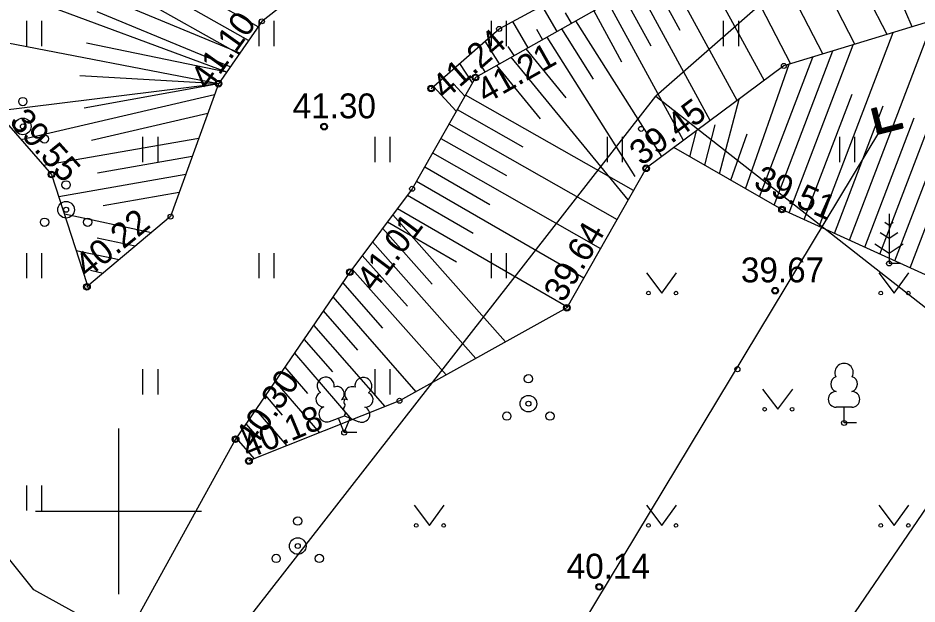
# Model space of a CAD drawing. Extents: x 641898 to 642452, y 6471715 to 6472255.
# Drawn here: x 641996.97 to 642024.06, y 6472097.21 to 6472114.87 of the extents above; entities that cross this region are included whole.
import ezdxf

# ---------------------------------------------------------------- set-up
doc = ezdxf.new("R2010")
doc.units = 0
for name, color, linetype in [('HALJASTUS', 7, 'Continuous'), ('KORGUS-EH2000', 7, 'Continuous'), ('MOOTMPUNKT', 7, 'Continuous'), ('MOOTPIIR', 7, 'Continuous'), ('PIIR', 7, 'Continuous'), ('PUU', 7, 'Continuous'), ('RELJEEF', 7, 'Continuous'), ('SKTRASS', 7, 'Continuous'), ('VORK', 7, 'Continuous')]:
    doc.layers.add(name, color=color, linetype=linetype)

msp = doc.modelspace()

# ---------------------------------------------------------------- linework, layer by layer
at = {"layer": 'HALJASTUS'}
for p, q in [((641997.225, 6472114.782), (641997.225, 6472114.021)), ((641997.68, 6472114.782), (641997.68, 6472114.021)), ((642004.225, 6472114.782), (642004.225, 6472114.021)), ((642004.68, 6472114.782), (642004.68, 6472114.021)), ((642011.225, 6472114.782), (642011.225, 6472114.021)), ((642011.68, 6472114.782), (642011.68, 6472114.021)), ((642018.225, 6472114.782), (642018.225, 6472114.021)), ((642018.68, 6472114.782), (642018.68, 6472114.021)), ((642000.725, 6472111.282), (642000.725, 6472110.521)), ((642001.18, 6472111.282), (642001.18, 6472110.521)), ((642007.725, 6472111.282), (642007.725, 6472110.521)), ((642008.18, 6472111.282), (642008.18, 6472110.521)), ((642014.725, 6472111.282), (642014.725, 6472110.521)), ((642015.18, 6472111.282), (642015.18, 6472110.521)), ((642021.725, 6472111.282), (642021.725, 6472110.521)), ((642022.18, 6472111.282), (642022.18, 6472110.521)), ((641997.225, 6472107.782), (641997.225, 6472107.021)), ((641997.68, 6472107.782), (641997.68, 6472107.021)), ((642004.225, 6472107.782), (642004.225, 6472107.021)), ((642004.68, 6472107.782), (642004.68, 6472107.021)), ((642011.225, 6472107.782), (642011.225, 6472107.021)), ((642011.68, 6472107.782), (642011.68, 6472107.021)), ((642015.908, 6472107.182), (642016.371, 6472106.575)), ((642016.371, 6472106.575), (642016.817, 6472107.182)), ((642022.908, 6472107.182), (642023.371, 6472106.575)), ((642023.371, 6472106.575), (642023.817, 6472107.182)), ((642000.725, 6472104.282), (642000.725, 6472103.521)), ((642001.18, 6472104.282), (642001.18, 6472103.521)), ((642007.725, 6472104.282), (642007.725, 6472103.521)), ((642008.18, 6472104.282), (642008.18, 6472103.521)), ((642019.408, 6472103.682), (642019.871, 6472103.075)), ((642019.871, 6472103.075), (642020.317, 6472103.682)), ((641997.225, 6472100.782), (641997.225, 6472100.021)), ((641997.68, 6472100.782), (641997.68, 6472100.021)), ((642008.908, 6472100.182), (642009.371, 6472099.575)), ((642009.371, 6472099.575), (642009.817, 6472100.182)), ((642015.908, 6472100.182), (642016.371, 6472099.575)), ((642016.371, 6472099.575), (642016.817, 6472100.182)), ((642022.908, 6472100.182), (642023.371, 6472099.575)), ((642023.371, 6472099.575), (642023.817, 6472100.182))]:
    msp.add_line(p, q, dxfattribs=at)
msp.add_lwpolyline([(642003.529, 6472102.174), (642000.861, 6472097.337), (641998.193, 6472092.499)], dxfattribs=at)
for centre in [(642015.97, 6472106.575), (642016.799, 6472106.575), (642022.97, 6472106.575), (642023.799, 6472106.575), (642019.47, 6472103.075), (642020.299, 6472103.075), (642008.97, 6472099.575), (642009.799, 6472099.575), (642015.97, 6472099.575), (642016.799, 6472099.575), (642022.97, 6472099.575), (642023.799, 6472099.575)]:
    msp.add_circle(centre, 0.055, dxfattribs=at)
at = {"layer": 'KORGUS-EH2000'}
for centre in [(642003.015, 6472112.887), (642010.755, 6472113.076), (642009.422, 6472112.742), (642006.193, 6472111.593), (642015.898, 6472110.337), (641997.98, 6472110.147), (642019.993, 6472109.094), (642006.969, 6472107.208), (641999.049, 6472106.763), (642019.787, 6472106.649), (642013.512, 6472106.135), (642003.529, 6472102.174), (642003.93, 6472101.516), (642014.487, 6472097.721)]:
    msp.add_circle(centre, 0.1, dxfattribs=at)
at = {"layer": 'MOOTMPUNKT'}
for centre in [(642004.319, 6472114.766), (642011.469, 6472114.538), (642020.049, 6472113.422), (642010.755, 6472113.076), (642003.015, 6472112.887), (642009.422, 6472112.742), (641997.116, 6472111.599), (642006.193, 6472111.593), (642015.746, 6472111.526), (642022.933, 6472111.454), (642015.898, 6472110.337), (641997.98, 6472110.147), (642008.847, 6472109.72), (641998.42, 6472109.088), (642001.569, 6472108.88), (642019.993, 6472109.094), (642006.969, 6472107.208), (642023.219, 6472107.468), (641999.049, 6472106.763), (642019.787, 6472106.649), (642013.512, 6472106.135), (642018.65, 6472104.28), (642008.467, 6472103.33), (642012.351, 6472103.243), (642021.863, 6472102.662), (642006.801, 6472102.371), (642003.529, 6472102.174), (642003.93, 6472101.516), (642005.4, 6472098.953), (642014.487, 6472097.721)]:
    msp.add_circle(centre, 0.075, dxfattribs=at)
at = {"layer": 'MOOTPIIR'}
msp.add_lwpolyline([(642014.306, 6472085.384), (642027.67, 6472104.979), (642055.501, 6472084.843), (642081.563, 6472094.262), (642123.938, 6472142.273), (642065.721, 6472244.475), (642008.922, 6472196.948), (642003.347, 6472200.453), (641979.65, 6472162.756), (641979.65, 6472162.756), (641986.045, 6472158.736), (642004.269, 6472142.365), (641987.048, 6472123.488), (641970.482, 6472097.889), (641986.758, 6472084.396)], close=True, dxfattribs=at)
at = {"layer": 'PIIR'}
for p, q in [((642094.72, 6472181.39), (642016.19, 6472112.51)), ((642002.45, 6472094.89), (642016.19, 6472112.51)), ((642016.19, 6472112.51), (642089.96, 6472054.66)), ((641997.45, 6472097.63), (641993.3, 6472102.74)), ((642002.45, 6472094.89), (641997.45, 6472097.63))]:
    msp.add_line(p, q, dxfattribs=at)
at = {"layer": 'PUU'}
for p, q in [((642023.219, 6472108.968), (642023.219, 6472107.468)), ((642023.219, 6472108.618), (642023.095, 6472108.701)), ((642023.343, 6472108.701), (642023.219, 6472108.618)), ((642023.219, 6472108.218), (642022.952, 6472108.396)), ((642023.486, 6472108.396), (642023.219, 6472108.218)), ((642022.795, 6472108.057), (642023.219, 6472107.775)), ((642023.219, 6472107.775), (642023.643, 6472108.057)), ((642023.579, 6472107.468), (642023.219, 6472107.468)), ((642022.103, 6472103.137), (642021.623, 6472103.137)), ((642021.863, 6472102.662), (642021.863, 6472103.137)), ((642006.361, 6472102.706), (642006.806, 6472102.881)), ((642006.801, 6472102.371), (642006.626, 6472102.811)), ((642006.801, 6472102.371), (642006.981, 6472102.811)), ((642006.806, 6472102.881), (642007.246, 6472102.701)), ((642022.243, 6472102.662), (642021.863, 6472102.662)), ((642007.181, 6472102.371), (642006.801, 6472102.371))]:
    msp.add_line(p, q, dxfattribs=at)
msp.add_lwpolyline([(642006.806, 6472103.376), (642006.786, 6472103.301), (642006.786, 6472103.281), (642006.796, 6472103.251), (642006.816, 6472103.216), (642006.821, 6472103.196), (642006.806, 6472103.161), (642006.781, 6472103.111), (642006.776, 6472103.086), (642006.781, 6472103.071), (642006.791, 6472103.041), (642006.826, 6472102.981), (642006.831, 6472102.961), (642006.826, 6472102.941), (642006.811, 6472102.906), (642006.806, 6472102.881)], dxfattribs=at)
for centre, radius in [((641997.116, 6472112.349), 0.125), ((641997.116, 6472111.599), 0.25), ((641997.766, 6472111.224), 0.125), ((641998.42, 6472109.838), 0.125), ((641998.42, 6472109.088), 0.25), ((641997.77, 6472108.713), 0.125), ((641999.07, 6472108.713), 0.125), ((642012.351, 6472103.993), 0.125), ((642012.351, 6472103.243), 0.25), ((642011.701, 6472102.868), 0.125), ((642013.001, 6472102.868), 0.125), ((642005.4, 6472099.703), 0.125), ((642005.4, 6472098.953), 0.25), ((642004.75, 6472098.578), 0.125), ((642006.05, 6472098.578), 0.125)]:
    msp.add_circle(centre, radius, dxfattribs=at)
for centre, radius, start, end in [((642021.863, 6472104.182), 0.277, 332.5799, 207.4201), ((642006.244, 6472103.785), 0.256, 350.4856, 111.5002), ((642007.38, 6472103.776), 0.256, 67.6168, 188.6314), ((642021.693, 6472103.835), 0.233, 109.0217, 253.1415), ((642022.033, 6472103.835), 0.233, 286.8508, 70.9859), ((642006.244, 6472103.785), 0.256, 111.5027, 232.5173), ((642006.579, 6472103.535), 0.224, 308.5041, 111.5725), ((642007.042, 6472103.53), 0.225, 67.7016, 230.5126), ((642007.38, 6472103.776), 0.256, 306.5997, 67.6143), ((642006.17, 6472103.374), 0.224, 111.4304, 274.4987), ((642007.447, 6472103.364), 0.224, 264.6183, 67.6866), ((642021.626, 6472103.374), 0.238, 90.0016, 269.3953), ((642022.1, 6472103.374), 0.238, 270.6047, 89.9984), ((642006.805, 6472103.138), 0.237, 66.7655, 111.5015), ((642006.275, 6472102.929), 0.237, 111.5014, 291.5004), ((642007.336, 6472102.921), 0.237, 247.6166, 67.6155)]:
    msp.add_arc(centre, radius, start, end, dxfattribs=at)
at = {"layer": 'RELJEEF'}
for p, q in [((642023.912, 6472114.6), (642021.981, 6472119.162)), ((642023.165, 6472114.373), (642020.963, 6472118.661)), ((642003.919, 6472114.19), (641996.111, 6472118.591)), ((642022.193, 6472114.076), (642020.065, 6472118.219)), ((642019.168, 6472117.777), (642021.221, 6472113.78)), ((642018.281, 6472117.316), (642020.249, 6472113.483)), ((642003.656, 6472113.811), (641995.446, 6472117.206)), ((642004.206, 6472114.603), (642000.235, 6472116.841)), ((642017.371, 6472116.803), (642019.453, 6472112.979)), ((642003.259, 6472113.239), (641995.155, 6472116.244)), ((642018.643, 6472112.377), (642016.499, 6472116.312)), ((642003.633, 6472113.778), (641999.744, 6472115.969)), ((642016.064, 6472116.067), (642016.916, 6472114.502)), ((642017.832, 6472111.775), (642015.628, 6472115.821)), ((642015.192, 6472115.576), (642016.038, 6472114.023)), ((642013.216, 6472114.462), (642012.763, 6472115.237)), ((642017.022, 6472111.172), (642014.757, 6472115.33)), ((642003.365, 6472113.391), (641999.355, 6472115.049)), ((642013.651, 6472114.708), (642013.466, 6472115.025)), ((642014.321, 6472115.085), (642015.16, 6472113.545)), ((642012.344, 6472113.971), (642011.882, 6472114.761)), ((642016.376, 6472110.693), (642013.784, 6472114.783)), ((642022.029, 6472108.167), (642024.518, 6472114.696)), ((642003.015, 6472112.887), (641995.086, 6472114.406)), ((642012.78, 6472114.217), (642012.603, 6472114.52)), ((642013.348, 6472114.537), (642014.306, 6472113.025)), ((642021.118, 6472108.582), (642023.346, 6472114.428)), ((642022.941, 6472107.752), (642025.541, 6472114.572)), ((642023.853, 6472107.337), (642026.564, 6472114.448)), ((642003.259, 6472113.239), (641999.032, 6472114.106)), ((642011.485, 6472113.487), (642011.046, 6472114.167)), ((642015.572, 6472110.094), (642012.912, 6472114.291)), ((642020.206, 6472108.997), (642022.135, 6472114.058)), ((642011.922, 6472113.733), (642011.743, 6472114.009)), ((642012.276, 6472113.933), (642013.483, 6472112.46)), ((642019.759, 6472109.228), (642021.529, 6472113.874)), ((642015.357, 6472109.384), (642011.834, 6472113.684)), ((642019.319, 6472109.48), (642020.924, 6472113.689)), ((642010.664, 6472112.916), (642010.286, 6472113.5)), ((642011.049, 6472113.242), (642010.903, 6472113.467)), ((642011.392, 6472113.435), (642012.709, 6472111.826)), ((642018.894, 6472109.723), (642020.209, 6472113.471)), ((642003.015, 6472112.887), (641998.831, 6472113.127)), ((642003.015, 6472112.887), (641996.316, 6472112.052)), ((642003.015, 6472112.887), (641998.961, 6472112.151)), ((642010.175, 6472112.056), (642009.49, 6472112.802)), ((642010.434, 6472112.512), (642010.101, 6472112.875)), ((642002.893, 6472112.549), (641997.062, 6472111.198)), ((642015.516, 6472109.664), (642010.453, 6472112.544)), ((642020.662, 6472108.79), (642022.104, 6472112.575)), ((642018.114, 6472110.17), (642018.701, 6472112.42)), ((642021.573, 6472108.374), (642023.039, 6472112.219)), ((642002.691, 6472111.989), (641999.187, 6472111.177)), ((642010.206, 6472112.11), (642012.181, 6472110.986)), ((642009.958, 6472111.675), (642015.022, 6472108.794)), ((642017.664, 6472110.428), (642017.982, 6472111.648)), ((642022.485, 6472107.959), (642023.973, 6472111.862)), ((642017.214, 6472110.685), (642017.419, 6472111.467)), ((642018.453, 6472109.976), (642018.945, 6472111.38)), ((642023.397, 6472107.544), (642024.908, 6472111.506)), ((642002.419, 6472111.235), (641997.744, 6472110.417)), ((642009.711, 6472111.24), (642011.687, 6472110.116)), ((642009.464, 6472110.806), (642014.528, 6472107.924)), ((642002.223, 6472110.694), (641999.367, 6472110.194)), ((642009.226, 6472110.386), (642011.189, 6472109.249)), ((642002.028, 6472110.152), (641998.197, 6472109.482)), ((642008.979, 6472109.951), (642014.021, 6472107.031)), ((642001.832, 6472109.61), (641999.54, 6472109.209)), ((642008.706, 6472109.532), (642010.688, 6472108.383)), ((642000.991, 6472108.395), (641998.369, 6472108.952)), ((642008.261, 6472108.937), (642011.663, 6472105.107)), ((642008.405, 6472109.128), (642013.527, 6472106.161)), ((642008.103, 6472108.725), (642010.187, 6472107.518)), ((642007.956, 6472108.528), (642009.452, 6472106.844)), ((642000.506, 6472107.987), (641999.361, 6472108.23)), ((642007.65, 6472108.119), (642010.768, 6472104.609)), ((642000.02, 6472107.579), (641998.726, 6472107.854)), ((642007.344, 6472107.71), (642008.704, 6472106.18)), ((642007.039, 6472107.301), (642009.873, 6472104.112)), ((641999.535, 6472107.171), (641999.153, 6472107.252)), ((641999.049, 6472106.763), (641999.084, 6472106.756)), ((642006.754, 6472106.893), (642007.954, 6472105.518)), ((642006.462, 6472106.467), (642008.961, 6472103.605)), ((642006.171, 6472106.04), (642007.201, 6472104.86)), ((642005.879, 6472105.614), (642008.027, 6472103.154)), ((642005.588, 6472105.187), (642006.448, 6472104.203)), ((642005.3, 6472104.766), (642007.035, 6472102.758)), ((642005.009, 6472104.339), (642005.692, 6472103.548)), ((642004.717, 6472103.912), (642006.053, 6472102.365)), ((642004.425, 6472103.485), (642004.935, 6472102.895)), ((642004.133, 6472103.058), (642005.071, 6472101.972)), ((642003.841, 6472102.631), (642004.178, 6472102.241)), ((642003.549, 6472102.204), (642004.089, 6472101.579))]:
    msp.add_line(p, q, dxfattribs=at)
for points in [[(642049.525, 6472147.752), (642033.209, 6472131.238), (642029.368, 6472128.57), (642019.347, 6472123.425), (642009.733, 6472118.353), (642006.276, 6472116.303), (642004.319, 6472114.766), (642003.015, 6472112.887), (642001.569, 6472108.88), (641999.049, 6472106.763)], [(642009.422, 6472112.742), (642011.469, 6472114.538), (642021.273, 6472119.831), (642030.743, 6472124.628), (642039.752, 6472128.982), (642050.967, 6472134.85), (642058.208, 6472138.912), (642059.402, 6472139.059), (642060.171, 6472138.313), (642060.027, 6472137.169), (642058.959, 6472136.054), (642051.674, 6472131.646), (642042.143, 6472126.699), (642035.655, 6472123.419), (642032.765, 6472119.235), (642026.028, 6472115.246), (642020.049, 6472113.422), (642015.898, 6472110.337), (642013.512, 6472106.135), (642008.467, 6472103.33), (642003.93, 6472101.516)], [(642058.721, 6472137.77), (642054.392, 6472134.892), (642048.445, 6472131.824), (642038.57, 6472127.238), (642029.307, 6472122.768), (642018.627, 6472117.511), (642010.755, 6472113.076), (642008.847, 6472109.72), (642006.969, 6472107.208), (642003.529, 6472102.174)], [(641995.53, 6472112.953), (641997.98, 6472110.147), (641999.049, 6472106.863)], [(642046.898, 6472092.573), (642045.899, 6472093.597), (642045.866, 6472095.265), (642040.033, 6472099.108), (642035.046, 6472103.249), (642029.201, 6472104.902), (642019.993, 6472109.094), (642016.735, 6472110.959)]]:
    msp.add_lwpolyline(points, dxfattribs=at)
at = {"layer": 'SKTRASS'}
for p, q in [((642022.829, 6472112.157), (642022.691, 6472112.122)), ((642022.828, 6472112.157), (642022.76, 6472111.85)), ((642022.829, 6472112.157), (642022.985, 6472111.54)), ((642022.691, 6472112.122), (642022.881, 6472111.368)), ((642022.719, 6472112.129), (642022.705, 6472112.066)), ((642022.747, 6472112.136), (642022.719, 6472112.012)), ((642022.774, 6472112.143), (642022.732, 6472111.958)), ((642022.801, 6472112.15), (642022.746, 6472111.904)), ((642022.76, 6472112.14), (642022.933, 6472111.454)), ((642022.842, 6472112.105), (642022.773, 6472111.796)), ((642022.856, 6472112.051), (642022.787, 6472111.742)), ((642022.869, 6472111.997), (642022.8, 6472111.689)), ((642022.883, 6472111.944), (642022.814, 6472111.635)), ((642022.896, 6472111.89), (642022.828, 6472111.581)), ((642022.91, 6472111.836), (642022.841, 6472111.527)), ((642022.924, 6472111.782), (642022.855, 6472111.473)), ((642022.937, 6472111.728), (642022.868, 6472111.419)), ((642022.951, 6472111.674), (642022.882, 6472111.368)), ((642022.964, 6472111.62), (642022.91, 6472111.375)), ((642022.933, 6472111.454), (642023.619, 6472111.627)), ((642022.985, 6472111.54), (642023.601, 6472111.696)), ((642023.27, 6472111.612), (642023.235, 6472111.457)), ((642023.297, 6472111.619), (642023.263, 6472111.464)), ((642023.324, 6472111.626), (642023.29, 6472111.471)), ((642023.352, 6472111.633), (642023.317, 6472111.477)), ((642023.379, 6472111.64), (642023.344, 6472111.484)), ((642023.406, 6472111.647), (642023.371, 6472111.491)), ((642023.433, 6472111.654), (642023.398, 6472111.498)), ((642023.46, 6472111.66), (642023.425, 6472111.505)), ((642023.487, 6472111.667), (642023.453, 6472111.512)), ((642023.514, 6472111.674), (642023.48, 6472111.519)), ((642023.542, 6472111.681), (642023.507, 6472111.525)), ((642023.569, 6472111.688), (642023.534, 6472111.532)), ((642023.596, 6472111.695), (642023.561, 6472111.539)), ((642023.612, 6472111.653), (642023.588, 6472111.546)), ((642023.601, 6472111.696), (642023.636, 6472111.558)), ((642022.933, 6472111.454), (642010.778, 6472091.299)), ((642022.881, 6472111.368), (642023.636, 6472111.558)), ((642022.978, 6472111.566), (642022.937, 6472111.382)), ((642022.999, 6472111.544), (642022.964, 6472111.388)), ((642023.026, 6472111.551), (642022.991, 6472111.395)), ((642023.053, 6472111.558), (642023.018, 6472111.402)), ((642023.08, 6472111.565), (642023.045, 6472111.409)), ((642023.107, 6472111.571), (642023.072, 6472111.416)), ((642023.134, 6472111.578), (642023.1, 6472111.423)), ((642023.162, 6472111.585), (642023.127, 6472111.429)), ((642023.189, 6472111.592), (642023.154, 6472111.436)), ((642023.216, 6472111.599), (642023.181, 6472111.443)), ((642023.243, 6472111.606), (642023.208, 6472111.45)), ((642023.626, 6472111.599), (642023.615, 6472111.553))]:
    msp.add_line(p, q, dxfattribs=at)
at = {"layer": 'VORK'}
for p, q in [((642000, 6472102.5), (642000, 6472097.5)), ((641997.5, 6472100), (642002.5, 6472100))]:
    msp.add_line(p, q, dxfattribs=at)

# ---------------------------------------------------------------- texts
at = {"layer": 'KORGUS-EH2000'}
for s, rotation, p in [('41.10', 54.3592, (642002.716, 6472112.664)), ('41.24', 41.1425, (642009.851, 6472112.385)), ('41.21', 29.4833, (642011.068, 6472112.269)), ('39.45', 36.6825, (642015.758, 6472110.392)), ('39.55', 312.0277, (641996.679, 6472111.724)), ('39.51', 336.1292, (642019.101, 6472109.768)), ('40.22', 39.331, (641999.068, 6472107)), ('41.01', 53.1448, (642007.709, 6472106.595)), ('39.64', 59.6018, (642013.411, 6472106.259)), ('40.30', 55.8631, (642004.082, 6472101.855)), ('40.18', 22.5419, (642003.908, 6472101.568))]:
    msp.add_text(s, height=0.75, rotation=rotation, dxfattribs=at).set_placement(p)
for s, p in [('41.30', (642005.248, 6472111.843)), ('39.67', (642018.754, 6472106.899)), ('40.14', (642013.504, 6472097.971))]:
    msp.add_text(s, height=0.75, dxfattribs=at).set_placement(p)

doc.saveas('drawing.dxf')
